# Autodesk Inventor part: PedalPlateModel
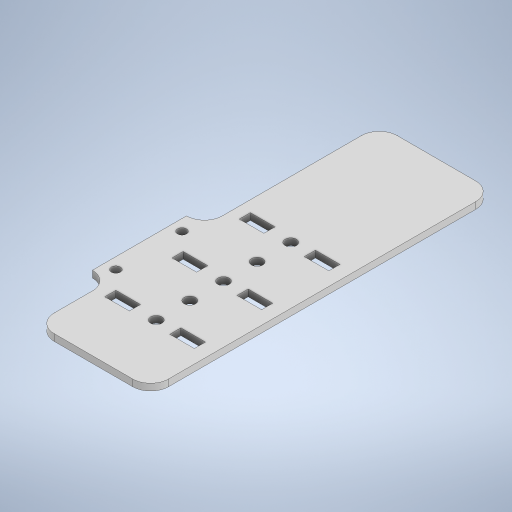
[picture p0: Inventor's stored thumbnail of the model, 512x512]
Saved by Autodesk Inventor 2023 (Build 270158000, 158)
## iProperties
Created: 2023-06
Part Number: PedalPlateModel
Material: Generic
Document SubType Name: Modeling
Designer: Admin
Density: 1 g/cm^3
Appearance: Default
Author: Admin
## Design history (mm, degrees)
sketch "Sketch1" dims "d75" = 4
  geometry: L1 (0, 0)-(60.249, 0); L2 (60.249, 0)-(60.249, -153); L3 (60.249, -153)-(0, -153); L4 (0, -153)-(0, 0); L5 (0, 0)-(51, 0); L6 (51, 0)-(51, -153); L7 (51, -153)-(0, -153); L8 (0, -153)-(0, 0); L9 (25.5, -28)-(25.5, -43); L10 (25.5, -43)-(25.5, -58); L11 (25.5, -58)-(25.5, -73); L12 (25.5, -73)-(25.5, -88); L13 (25.5, -28)-(25.5, 0); L14 (6, -25.5)-(17, -25.5); L15 (17, -25.5)-(17, -30.5); L16 (17, -30.5)-(6, -30.5); L17 (6, -30.5)-(6, -25.5); L18 (51, -33)-(59, -33); L19 (59, -33)-(59, -75); L20 (59, -75)-(51, -75); L21 (51, -75)-(51, -33); L22 (25.5, -11.002)-(0, -11.002); L23 (17, -60.5)-(6, -60.5); L24 (17, -55.5)-(17, -60.5); L25 (6, -55.5)-(17, -55.5); L26 (6, -60.5)-(6, -55.5); L27 (17, -90.5)-(6, -90.5); L28 (17, -85.5)-(17, -90.5); L29 (6, -85.5)-(17, -85.5); L30 (6, -90.5)-(6, -85.5); L31 (46, -30.5)-(35, -30.5); L32 (46, -25.5)-(46, -30.5); L33 (35, -25.5)-(46, -25.5); L34 (35, -30.5)-(35, -25.5); L35 (46, -60.5)-(35, -60.5); L36 (46, -55.5)-(46, -60.5); L37 (35, -55.5)-(46, -55.5); L38 (35, -60.5)-(35, -55.5); L39 (46, -90.5)-(35, -90.5); L40 (46, -85.5)-(46, -90.5); L41 (35, -85.5)-(46, -85.5); L42 (35, -90.5)-(35, -85.5); L43 (54, -40.5)-(25.5, -40.5); C1 r 2.5 at (25.5, -28); C2 r 2.5 at (25.5, -58); C3 r 2.5 at (25.5, -73); C4 r 2.5 at (25.5, -88); C5 r 2 at (54, -68); 2 further points; 1 other entity
  constraints: 78 end point, 9 equal length, 8 vertical alignment, 5 centre point, 5 collinear, 5 horizontal, 5 point on line, 4 perpendicular, 3 equal radius, 2 vertical, 1 midpoint, 1 tangent, 46 other
  dimensions: "d14" = 5 distance between parallel lines of L16 L14; "d19" = 11 distance between parallel lines of L17 L15; "d20" = 153 distance between parallel lines of L3 L5; "d23" = 51 distance between parallel lines of L4 L6; "d34" = 15 distance of L9.start L9.end; "d41" = 28 distance of L9.start L13.end; "d45" = 8 distance between parallel lines of L19 L6; "d46" = 5 diameter of C1; "d52" = 33 distance between parallel lines of L5 L18; "d53" = 42 distance of L18.end L19.end; "d63" = 6 distance between parallel lines of L4 L17; "d66" = 30 distance of L15.end L23.start; "d69" = 29 distance of L15.end L31.start; "d73" = 3 distance from line of L6 point (54, -38.5); "d77" = 29.5 distance of C5.centre point (54, -38.5)
extrude "Extrusion1" new body sketch "Sketch1" distance "d82" = 3; taper "d83" = 0 deg
fillet "Fillet1" dims "d84" = 8
body "Solid1"
node "Image2"
